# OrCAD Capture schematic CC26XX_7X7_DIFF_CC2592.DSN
size A3; title: TIDC-CC2650-CC2592-EMK; rev: Rev 1.1.0
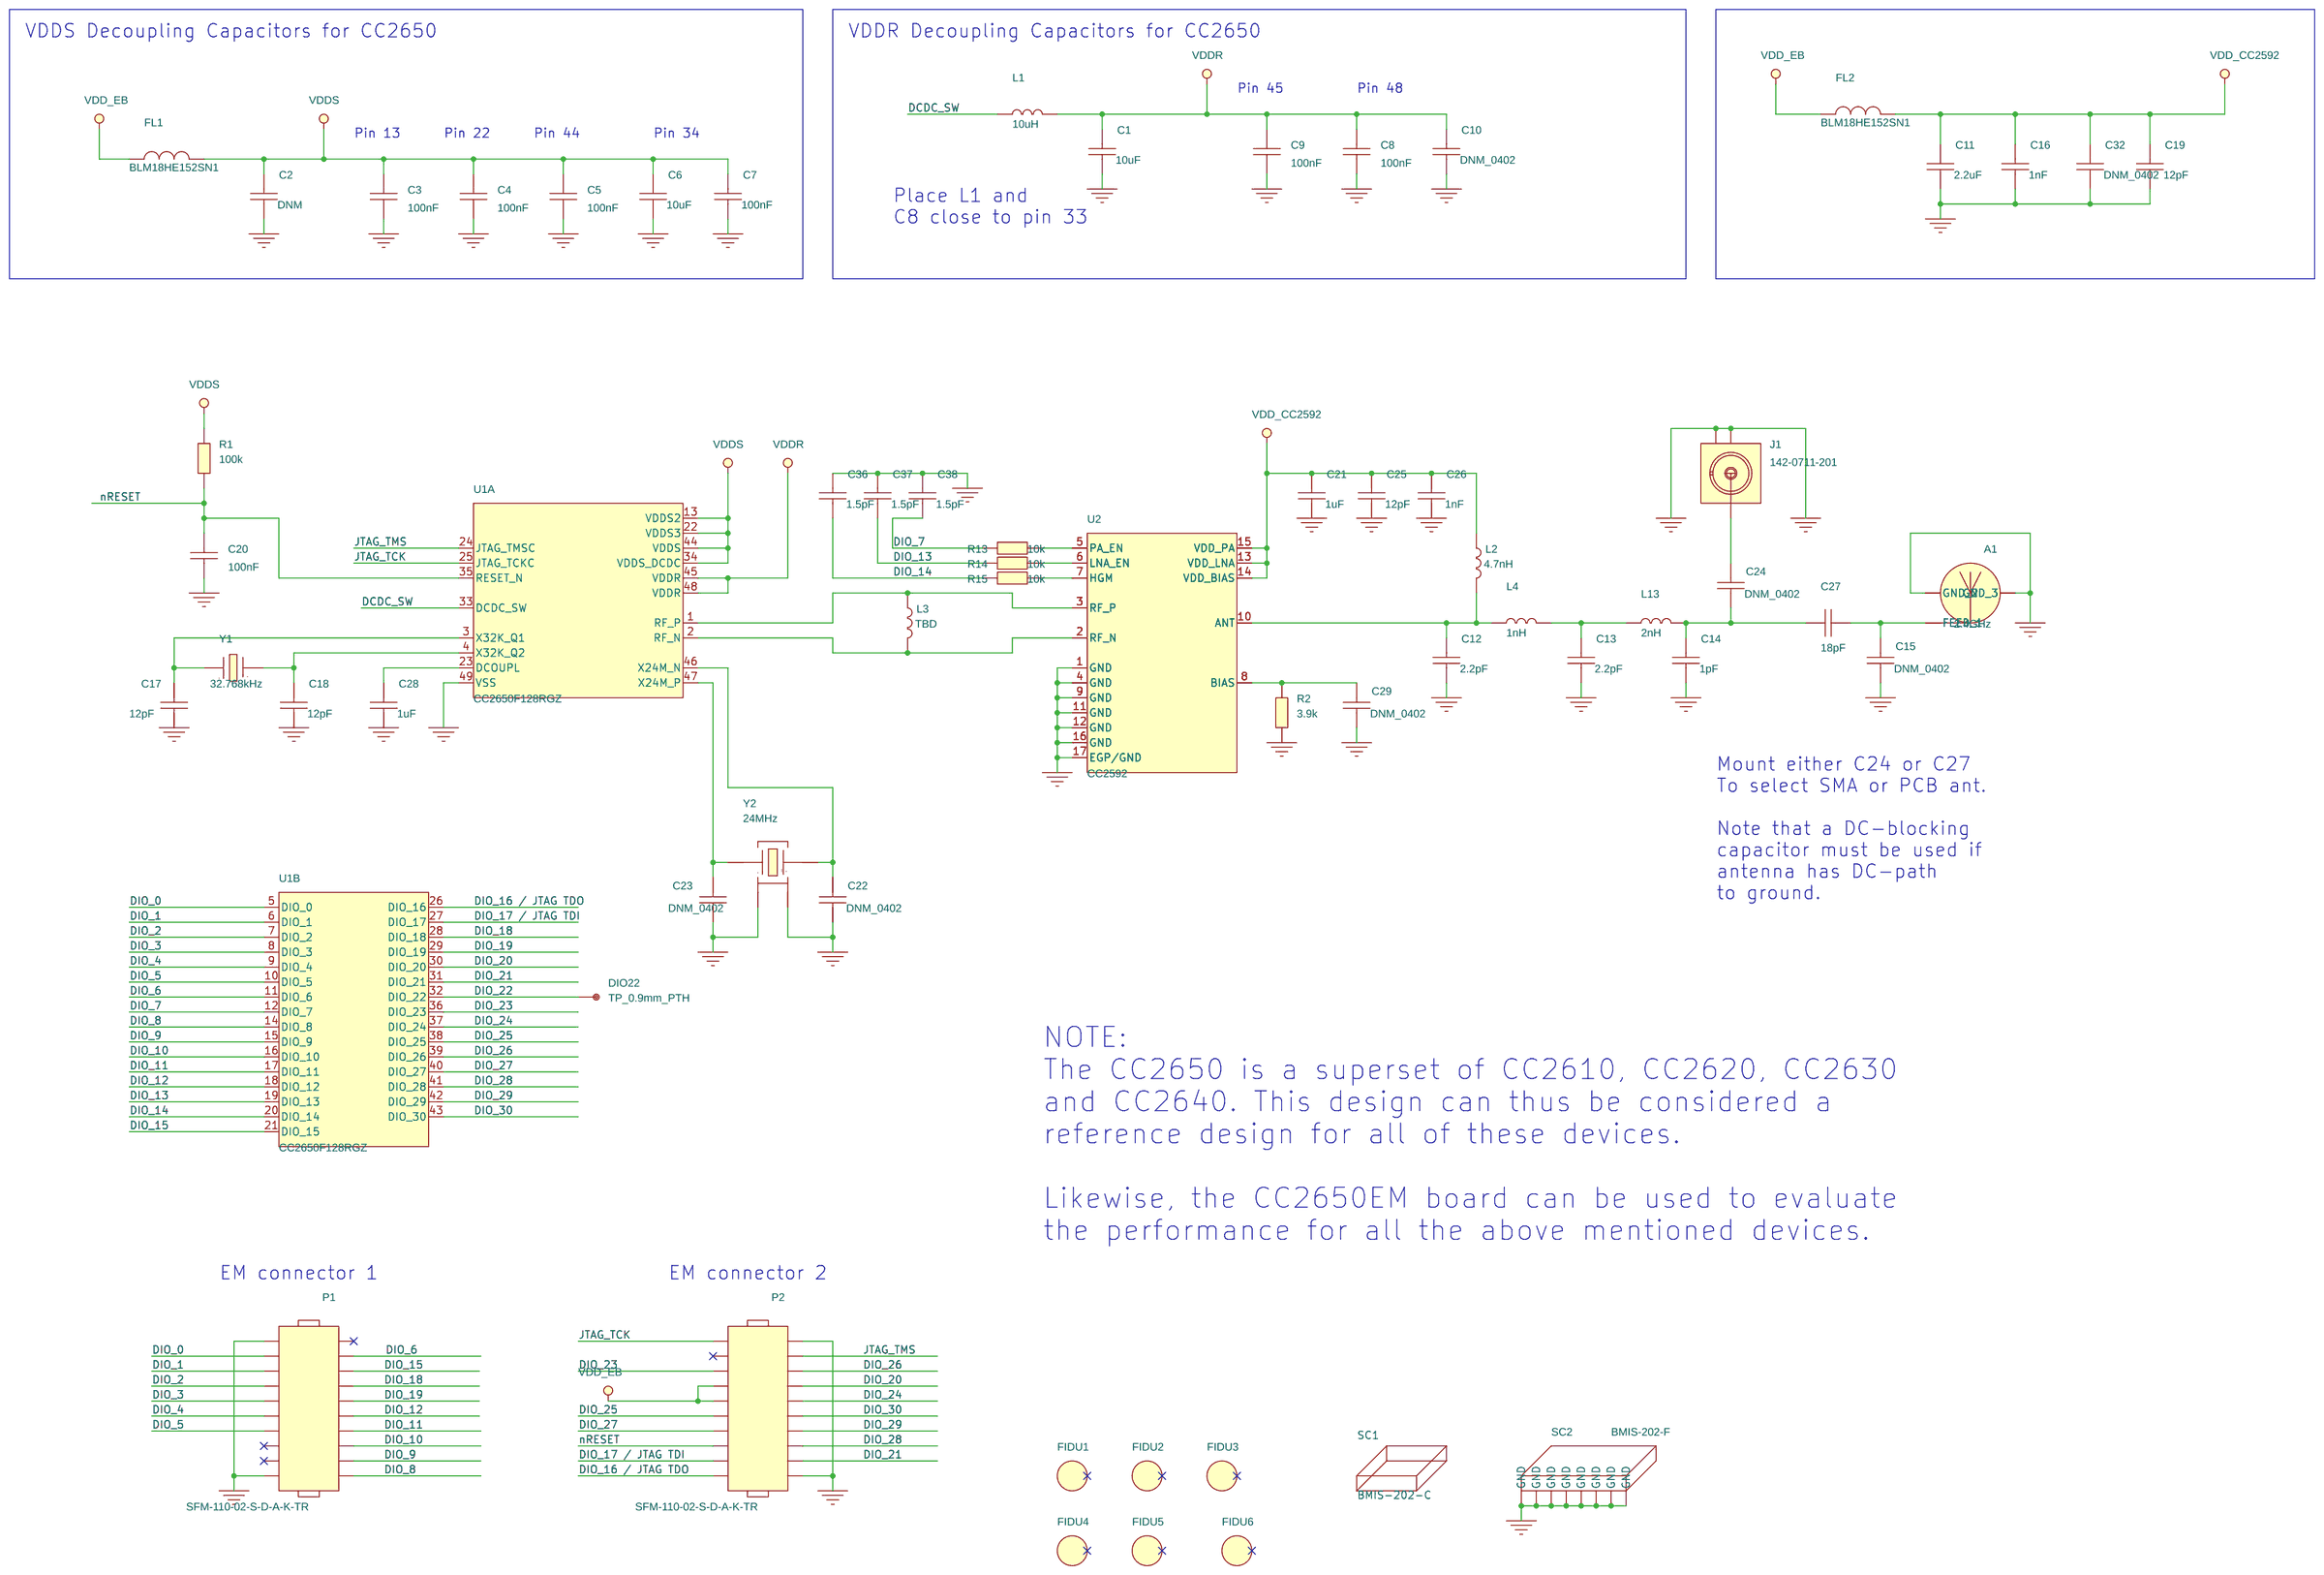
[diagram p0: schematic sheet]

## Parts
A1  2.4GHz  [ANTENNA_DN007N]
C1  10uF  [CAPC1608X90N]
C2  DNM  [CAPC1608X90N]
C3  100nF  [CAPC1005X60N]
C4  100nF  [CAPC1005X60N]
C5  100nF  [CAPC1005X60N]
C6  10uF  [CAPC1608X90N]
C7  100nF  [CAPC1608X90N]
C8  100nF  [CAPC1005X60N]
C9  100nF  [CAPC1005X60N]
C10  DNM_0402  [CAPC1005X60N]
C11  2.2uF  [CAPC1608X90N]
C12  2.2pF  [CAPC1005X60N]
C13  2.2pF  [CAPC1005X60N]
C14  1pF  [CAPC1005X60N]
C15  DNM_0402  [CAPC1005X60N]
C16  1nF  [CAPC1005X60N]
C17  12pF  [CAPC1005X60N]
C18  12pF  [CAPC1005X60N]
C19  12pF  [CAPC1005X60N]
C20  100nF  [CAPC1005X60N]
C21  1uF  [CAPC1005X60N]
C22  DNM_0402  [CAPC1005X60N]
C23  DNM_0402  [CAPC1005X60N]
C24  DNM_0402  [CAPC1005X60N]
C25  12pF  [CAPC1005X60N]
C26  1nF  [CAPC1005X60N]
C27  18pF  [CAPC1005X60N]
C28  1uF  [CAPC1005X60N]
C29  DNM_0402  [CAPC1005X60N]
C32  DNM_0402  [CAPC1005X60N]
C36  1.5pF  [CAPC1005X60N]
C37  1.5pF  [CAPC1005X60N]
C38  1.5pF  [CAPC1005X60N]
DIO22  TP_0.9mm_PTH  [TP150_90H]
FIDU1  FIDU_1MM  [FID100X115B]
FIDU2  FIDU_1MM  [FID100X115B]
FIDU3  FIDU_1MM  [FID100X115B]
FIDU4  FIDU_1MM  [FID100X115B]
FIDU5  FIDU_1MM  [FID100X115B]
FIDU6  FIDU_1MM  [FID100X115B]
FL1  BLM18HE152SN1  [FIL_BLM18HE152SN1DN]
FL2  BLM18HE152SN1  [FIL_BLM18HE152SN1DN]
J1  142-0711-201  [CINCH_1420711201_A2N]
L1  10uH  [INDC2012X150N]
L2  4.7nH  [INDC1005X60N]
L3  TBD  [INDC1005X60N]
L4  1nH  [INDC1005X60N]
L13  2nH  [INDC1005X60N]
P1  SFM-110-02-S-D-A-K-TR  [SAMTEC_SFM11002AN]
P2  SFM-110-02-S-D-A-K-TR  [SAMTEC_SFM11002AN]
R1  100k  [RESC1005X40N]
R2  3.9k  [RESC1005X40N]
R13  10k  [RESC1005X40N]
R14  10k  [RESC1005X40N]
R15  10k  [RESC1005X40N]
SC1  BMIS-202-C  [MECH_BMIS202CN]
SC2  BMIS-202-F  [MECH_BMIS202FN]
U1  CC2650F128RGZ  [QFNFC50P700X700X80-49CN]  (sections A,B)
U2  CC2592  [QFNFC65P400X400X100-17AN]
Y1  32.768kHz  [XTAL_FC-135N]
Y2  24MHz  [OSCCC250X320X60-4N]

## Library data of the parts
A1 = ANTENNA_DN007: ANTENNA, NON COMPONENT, 2.4GHz INVERTED F ANTENNA, NOT APPLY; AutoDoc File: http://notefied-dynamic-precision.com/DB/Apps/Desktop/Item/Object.aspx?id=85542; Budget Currency: N/A; Budget Price: N/A; Datasheet URL 1: N/A; Datasheet URL 2: http://www.ti.com/lit/an/swru120b/swru120b.pdf; Definied Quality: INDUSTRIAL; Esd Level: N/A; FPLIST: ANTENNA_DN007N,ANTENNA_DN007AN; Last Time Buy: N/A; Lead Time: N/A; LifeCycle Status: ACTIVE; MPN: DN007; MPN Status: ACTIVE; MSL: N/A; MTBF: N/A; MTBF Standard: N/A; Manufacturer: TEXAS INSTRUMENTS; Max Oper Temp: +85DEGC; Min Oper Temp: -40DEGC; Mounting Type: NOT APPLY; NOTE Status: PREFERRED; Old Footprint: ANTENNA_DN007N,ANTENNA_DN007AN; Packing Size: N/A; Packing Type: N/A; Part Number: 13-00347; Part Type: MECHANIC\ANTENNA\NON_COMPONENT; Revision: R008; RoHS Status: NOT_APPLICABLE; WEIGHT: N/A
C1 C6 = CAPACITOR: CAPACITOR, CERAMIC X5R, 10uF, 6.3V, -20%/+20%, -55DEGC/+85DEGC, 0603, SMD; ALT_SYMBOLS: CAPC1608X90L,CAPC1608X90M; AutoDoc File: http://notefied-dynamic-precision.com/DB/Apps/Desktop/Item/Object.aspx?id=74686; Budget Currency: EUR; Budget Price: 0.113; Datasheet URL 1: http://search.murata.co.jp/Ceramy/image/img/w_hinm/L0005E.pdf; Datasheet URL 2: http://psearch.murata.com/capacitor/product/GRM188R60J106ME47%23.pdf; Definied Quality: INDUSTRIAL; Dielectric Type: X5R; Esd Level: N/A; FPLIST: CAPC1608X90N,CAPC1608X90L,CAPC1608X90M; Last Time Buy: N/A; Lead Time: 20; LifeCycle Status: NRND; MPN: GRM188R60J106ME47D; MPN Status: NRND; MSL: 1; MTBF: N/A; MTBF Standard: N/A; Manufacturer: MURATA; Max Oper Temp: +85DEGC; Max Tol: +20%; Min Oper Temp: -55DEGC; Min Tol: -20%; Mounting Type: SMD; NOTE Status: PREFERRED; PCB Package: 0603; Packing Size: 4000; Packing Type: TAPE_&_REEL; Part Number: 02-02419; Part Type: CAPACITOR\CERAMIC\0603\STANDARD; Revision: R003; RoHS Status: ROHS_COMPLIANT; Rtd Voltage: 6.3V; WEIGHT: 0.0063g
C2 = CAPACITOR: CAPACITOR, DO NOT MOUNT, 0603, SMD; ALT_SYMBOLS: CAPC1608X90L,CAPC1608X90M; AutoDoc File: http://notefied-dynamic-precision.com/DB/Apps/Desktop/Item/Object.aspx?id=50475; FPLIST: CAPC1608X90N,CAPC1608X90L,CAPC1608X90M; Old Footprint: CAPC1608X90N,0603; Part Number: 02-01324; Part Type: NON_COMPONENT\DNM; Revision: R003
C3-C5 C8 C9 C20 = CAPACITOR: CAPACITOR, CERAMIC X7R, 100nF, 6.3V, -10%/+10%, -55DEGC/+125DEGC, 0402, SMD; ALT_SYMBOLS: CAPC1005X60L,CAPC1005X60M; AutoDoc File: http://notefied-dynamic-precision.com/DB/Apps/Desktop/Item/Object.aspx?id=73748; Budget Currency: EUR; Budget Price: 0.007; Datasheet URL 1: http://search.murata.co.jp/Ceramy/image/img/w_hinm/L0005E.pdf; Datasheet URL 2: http://psearch.murata.com/capacitor/product/GRM155R70J104KA01%23.pdf; Definied Quality: INDUSTRIAL; Dielectric Type: X7R; Esd Level: N/A; FPLIST: CAPC1005X60N,CAPC1005X60L,CAPC1005X60M; Last Time Buy: N/A; Lead Time: 14; LifeCycle Status: NRND; MPN: GRM155R70J104KA01D; MPN Status: NRND; MSL: 1; MTBF: N/A; MTBF Standard: N/A; Manufacturer: MURATA; Max Oper Temp: +125DEGC; Max Tol: +10%; Min Oper Temp: -55DEGC; Min Tol: -10%; Mounting Type: SMD; NOTE Status: PREFERRED; Old Footprint: CAPC1005X60N,0402; PCB Package: 0402; Packing Size: 10000; Packing Type: TAPE_&_REEL; Part Number: 02-02323; Part Type: CAPACITOR\CERAMIC\0402\STANDARD; Revision: R000; RoHS Status: ROHS_COMPLIANT; Rtd Voltage: 6.3V; WEIGHT: 0.0016g
C7 = CAPACITOR: CAPACITOR, CERAMIC X7R, 100nF, 25V, -10%/+10%, -55DEGC/+125DEGC, 0603, SMD; ALT_SYMBOLS: CAPC1608X90L,CAPC1608X90M; AutoDoc File: http://notefied-dynamic-precision.com/DB/Apps/Desktop/Item/Object.aspx?id=72070; Budget Currency: EUR; Budget Price: 0.005; Cage Code: C0151; Datasheet URL 1: http://search.murata.co.jp/Ceramy/image/img/w_hinm/L0005E.pdf; Datasheet URL 2: http://psearch.murata.com/capacitor/product/GRM188R71E104KA01%23.pdf; Definied Quality: INDUSTRIAL; Dielectric Type: X7R; Esd Level: N/A; FPLIST: CAPC1608X90N,CAPC1608X90L,CAPC1608X90M; Last Time Buy: N/A; Lead Time: 15; LifeCycle Status: NRND; MPN: GRM188R71E104KA01D; MPN Status: NRND; MSL: 1; MTBF: N/A; MTBF Standard: N/A; Manufacturer: MURATA; Max Oper Temp: +125DEGC; Max Tol: +10%; Min Oper Temp: -55DEGC; Min Tol: -10%; Mounting Type: SMD; NOTE Status: PREFERRED; Old Footprint: CAPC1608X90N,0603; PCB Package: 0603; Packing Size: 4000; Packing Type: TAPE_&_REEL; Part Number: 02-01992; Part Type: CAPACITOR\CERAMIC\0603\STANDARD; Revision: R001; RoHS Status: ROHS_COMPLIANT; Rtd Voltage: 25V; WEIGHT: 0.0063g
C10 C15 C22-C24 C29 = CAPACITOR: CAPACITOR, CERAMIC, TBD, -55DEGC/+125DEGC, 0402, DNM, SMD; ALT_SYMBOLS: CAPC1005X60L,CAPC1005X60M; AutoDoc File: http://notefied-dynamic-precision.com/DB/Apps/Desktop/Item/Object.aspx?id=84862; Budget Currency: USD; Budget Price: 0.00589; Datasheet URL 1: N/A; Datasheet URL 2: N/A; Definied Quality: INDUSTRIAL; Dielectric Type: MISSING-INFO; Esd Level: N/A; FPLIST: CAPC1005X60N,CAPC1005X60L,CAPC1005X60M; Last Time Buy: N/A; Lead Time: N/A; LifeCycle Status: ACTIVE; MPN: CAPACITOR_0402_DNM_N/A_M; MPN Status: ACTIVE; MSL: N/A; MTBF: N/A; MTBF Standard: N/A; Manufacturer: MANUFACTURER SELECTION; Max Oper Temp: +125DEGC; Min Oper Temp: -55DEGC; Mounting Type: SMD; NOTE Status: PREFERRED; PCB Package: 0402; Packing Size: 10000; Packing Type: TAPE_&_REEL; Part Number: 02-04164; Part Type: CAPACITOR\CERAMIC\0402\STANDARD; Revision: R000; RoHS Status: MISSING_INFO; WEIGHT: N/A
C11 = CAPACITOR: CAPACITOR, CERAMIC X5R, 2.2uF, 10V, -20%/+20%, -55DEGC/+85DEGC, 0603, SMD; ALT_SYMBOLS: CAPC1608X90L,CAPC1608X90M; AutoDoc File: http://notefied-dynamic-precision.com/DB/Apps/Desktop/Item/Object.aspx?id=50283; Budget Currency: EUR; Budget Price: 0.032; Datasheet URL 1: http://search.murata.co.jp/Ceramy/image/img/w_hinm/L0005E.pdf; Datasheet URL 2: http://psearch.murata.com/capacitor/product/GRM188R61A225ME34%23.pdf; Definied Quality: INDUSTRIAL; Dielectric Type: X5R; Esd Level: N/A; Last Time Buy: N/A; Lead Time: 20; LifeCycle Status: NRND; MPN: GRM188R61A225ME34D; MPN Status: NRND; MSL: 1; MTBF: N/A; MTBF Standard: N/A; Manufacturer: MURATA; Max Oper Temp: +85DEGC; Max Tol: +20%; Min Oper Temp: -55DEGC; Min Tol: -20%; Mounting Type: SMD; NOTE Status: PREFERRED; Old Footprint: CAPC1608X90N,0603; PCB Package: 0603; Packing Size: 4000; Packing Type: TAPE_&_REEL; Part Number: 02-01132; Part Type: CAPACITOR\CERAMIC\0603\STANDARD; Revision: R002; RoHS Status: ROHS_COMPLIANT; Rtd Voltage: 10V; WEIGHT: 0.0063g
C12 C13 = CAPACITOR: CAPACITOR, CERAMIC C0G/NP0, 2.2pF, 50V, -0.25pF/+0.25pF, -55DEGC/+125DEGC, 0402, SMD; ALT_SYMBOLS: CAPC1005X60L,CAPC1005X60M; AutoDoc File: http://notefied-dynamic-precision.com/DB/Apps/Desktop/Item/Object.aspx?id=87251; Budget Currency: EUR; Budget Price: 0.007; Datasheet URL 1: http://search.murata.co.jp/Ceramy/image/img/w_hinm/L0005E.pdf; Datasheet URL 2: http://psearch.murata.com/capacitor/product/GRM1555C1H2R2CA01%23.pdf; Definied Quality: INDUSTRIAL; Dielectric Type: C0G/NP0; Esd Level: N/A; Last Time Buy: N/A; Lead Time: 12; LifeCycle Status: ACTIVE; MPN: GRM1555C1H2R2CA01D; MPN Status: ACTIVE; MSL: 1; MTBF: N/A; MTBF Standard: N/A; Manufacturer: MURATA; Max Oper Temp: +125DEGC; Max Tol: +0.25pF; Min Oper Temp: -55DEGC; Min Tol: -0.25pF; Mounting Type: SMD; NOTE Status: PREFERRED; PCB Package: 0402; Packing Size: 10000; Packing Type: TAPE_&_REEL; Part Number: 02-04605; Part Type: CAPACITOR\CERAMIC\0402\STANDARD; Revision: R001; RoHS Status: ROHS_COMPLIANT; Rtd Voltage: 50V; WEIGHT: 0.0016g
C14 = CAPACITOR: CAPACITOR, CERAMIC C0G/NP0, 1pF, 50V, -0.25pF/ +0.25pF, -55DEGC/+125DEGC, 0402, SMD; ALT_SYMBOLS: CAPC1005X60L,CAPC1005X60M; AutoDoc File: http://notefied-dynamic-precision.com/DB/Apps/Desktop/Item/Object.aspx?id=87790; Budget Currency: EUR; Budget Price: 0.006; Datasheet URL 1: http://search.murata.co.jp/Ceramy/image/img/w_hinm/L0005E.pdf; Datasheet URL 2: http://psearch.murata.com/capacitor/product/GRM1555C1H1R0CA01%23.pdf; Definied Quality: INDUSTRIAL; Dielectric Type: C0G/NP0; Esd Level: N/A; Last Time Buy: N/A; Lead Time: 12; LifeCycle Status: ACTIVE; MPN: GRM1555C1H1R0CA01D; MPN Status: ACTIVE; MSL: 1; MTBF: N/A; MTBF Standard: N/A; Manufacturer: MURATA; Max Oper Temp: +125DEGC; Max Tol: +0.25pF; Min Oper Temp: -55DEGC; Min Tol: -0.25pF; Mounting Type: SMD; NOTE Status: PREFERRED; PCB Package: 0402; Packing Size: 10000; Packing Type: TAPE_&_REEL; Part Number: 02-04672; Part Type: CAPACITOR\CERAMIC\0402\STANDARD; Revision: R001; RoHS Status: ROHS_COMPLIANT; Rtd Voltage: 50V; WEIGHT: 0.0016g
C16 = CAPACITOR: CAPACITOR, CERAMIC X7R, 1nF, 50V, -5%/+5%, -55DEGC/+125DEGC, 0402, SMD; ALT_SYMBOLS: CAPC1005X60L,CAPC1005X60M; AutoDoc File: http://notefied-dynamic-precision.com/DB/Apps/Desktop/Item/Object.aspx?id=80112; Budget Currency: USD; Budget Price: 0.00589; Datasheet URL 1: N/A; Datasheet URL 2: N/A; Definied Quality: INDUSTRIAL; Dielectric Type: X7R; Esd Level: N/A; Last Time Buy: N/A; Lead Time: N/A; LifeCycle Status: ACTIVE; MPN: CAPACITOR_0402_1nF_X7R_M_+/-5%_50V; MPN Status: ACTIVE; MSL: N/A; MTBF: N/A; MTBF Standard: N/A; Manufacturer: MANUFACTURER SELECTION; Max Oper Temp: +125DEGC; Max Tol: +5%; Min Oper Temp: -55DEGC; Min Tol: -5%; Mounting Type: SMD; NOTE Status: PREFERRED; PCB Package: 0402; Packing Size: 10000; Packing Type: TAPE_&_REEL; Part Number: 02-03019; Part Type: CAPACITOR\CERAMIC\0402\STANDARD; Revision: R001; RoHS Status: ROHS_COMPLIANT; Rtd Voltage: 50V; WEIGHT: N/A
C17 C18 = CAPACITOR: CAPACITOR, CERAMIC C0G/NP0, 12pF, 50V, -5%/+5%, -55DEGC/+125DEGC, 0402, SMD; ALT_SYMBOLS: CAPC1005X60L,CAPC1005X60M; AutoDoc File: http://notefied-dynamic-precision.com/DB/Apps/Desktop/Item/Object.aspx?id=80123; Budget Currency: USD; Budget Price: 0.00589; Datasheet URL 1: N/A; Datasheet URL 2: N/A; Definied Quality: INDUSTRIAL; Dielectric Type: C0G/NP0; Esd Level: N/A; FPLIST: CAPC1005X60N,CAPC1005X60L,CAPC1005X60M; Last Time Buy: N/A; Lead Time: N/A; LifeCycle Status: ACTIVE; MPN: CAPACITOR_0402_12pF_C0G/NP0_M_+/-5%_50V; MPN Status: ACTIVE; MSL: N/A; MTBF: N/A; MTBF Standard: N/A; Manufacturer: MANUFACTURER SELECTION; Max Oper Temp: +125DEGC; Max Tol: +5%; Min Oper Temp: -55DEGC; Min Tol: -5%; Mounting Type: SMD; NOTE Status: PREFERRED; PCB Package: 0402; Packing Size: 10000; Packing Type: TAPE_&_REEL; Part Number: 02-03030; Part Type: CAPACITOR\CERAMIC\0402\STANDARD; Revision: R000; RoHS Status: ROHS_COMPLIANT; Rtd Voltage: 50V; WEIGHT: N/A
C19 C25 = CAPACITOR: CAPACITOR, CERAMIC C0G/NP0, 12pF, 50V, -5%/+5%, -55DEGC/+125DEGC, 0402, SMD; ALT_SYMBOLS: CAPC1005X60L,CAPC1005X60M; AutoDoc File: http://notefied-dynamic-precision.com/DB/Apps/Desktop/Item/Object.aspx?id=84867; Budget Currency: EUR; Budget Price: 0.007; Datasheet URL 1: http://search.murata.co.jp/Ceramy/image/img/w_hinm/L0005E.pdf; Datasheet URL 2: http://psearch.murata.com/capacitor/product/GRM1555C1H120JA01%23.pdf; Definied Quality: INDUSTRIAL; Dielectric Type: C0G/NP0; Esd Level: N/A; Last Time Buy: N/A; Lead Time: 12; LifeCycle Status: ACTIVE; MPN: GRM1555C1H120JA01D; MPN Status: ACTIVE; MSL: 1; MTBF: N/A; MTBF Standard: N/A; Manufacturer: MURATA; Max Oper Temp: +125DEGC; Max Tol: +5%; Min Oper Temp: -55DEGC; Min Tol: -5%; Mounting Type: SMD; NOTE Status: PREFERRED; PCB Package: 0402; Packing Size: 10000; Packing Type: TAPE_&_REEL; Part Number: 02-04168; Part Type: CAPACITOR\CERAMIC\0402\STANDARD; Revision: R000; RoHS Status: ROHS_COMPLIANT; Rtd Voltage: 50V; WEIGHT: 0.0016g
C21 = CAPACITOR: CAPACITOR, CERAMIC X5R, 1uF, 10V, -10%/+10%, -55DEGC/+85DEGC, 0402, SMD; ALT_SYMBOLS: CAPC1005X60L,CAPC1005X60M; AutoDoc File: http://notefied-dynamic-precision.com/DB/Apps/Desktop/Item/Object.aspx?id=74236; Budget Currency: EUR; Budget Price: 0.019; Datasheet URL 1: http://search.murata.co.jp/Ceramy/image/img/w_hinm/L0005E.pdf; Datasheet URL 2: http://psearch.murata.com/capacitor/product/GRM155R61A105KE15%23.pdf; Definied Quality: INDUSTRIAL; Dielectric Type: X5R; Esd Level: N/A; Last Time Buy: N/A; Lead Time: 12; LifeCycle Status: NRND; MPN: GRM155R61A105KE15D; MPN Status: NRND; MSL: 1; MTBF: N/A; MTBF Standard: N/A; Manufacturer: MURATA; Max Oper Temp: +85DEGC; Max Tol: +10%; Min Oper Temp: -55DEGC; Min Tol: -10%; Mounting Type: SMD; NOTE Status: PREFERRED; Old Footprint: CAPC1005X60N,0402; PCB Package: 0402; Packing Size: 10000; Packing Type: TAPE_&_REEL; Part Number: 02-02381; Part Type: CAPACITOR\CERAMIC\0402\STANDARD; Revision: R005; RoHS Status: ROHS_COMPLIANT; Rtd Voltage: 10V; WEIGHT: 0.0016g
C26 = CAPACITOR: CAPACITOR, CERAMIC C0G/NP0, 1nF, 50V, -5%/+5%, -55DEGC/+125DEGC, 0402, SMD; ALT_SYMBOLS: CAPC1005X60L,CAPC1005X60M; AutoDoc File: http://notefied-dynamic-precision.com/DB/Apps/Desktop/Item/Object.aspx?id=88013; Budget Currency: USD; Budget Price: 0.00589; Datasheet URL 1: N/A; Datasheet URL 2: N/A; Definied Quality: INDUSTRIAL; Dielectric Type: C0G/NP0; Esd Level: N/A; Last Time Buy: N/A; Lead Time: N/A; LifeCycle Status: ACTIVE; MPN: CAPACITOR_0402_1nF_C0G/NP0_M_+/-5%_50V; MPN Status: ACTIVE; MSL: N/A; MTBF: N/A; MTBF Standard: N/A; Manufacturer: MANUFACTURER SELECTION; Max Oper Temp: +125DEGC; Max Tol: +5%; Min Oper Temp: -55DEGC; Min Tol: -5%; Mounting Type: SMD; NOTE Status: PREFERRED; PCB Package: 0402; Packing Size: 10000; Packing Type: TAPE_&_REEL; Part Number: 02-04728; Part Type: CAPACITOR\CERAMIC\0402\STANDARD; Revision: R001; RoHS Status: ROHS_COMPLIANT; Rtd Voltage: 50V; WEIGHT: N/A
C27 = CAPACITOR: CAPACITOR, CERAMIC C0G/NPO, 18pF, 50V, -55DEGC/+125DEGC, 0402, SMD; ALT_SYMBOLS: CAPC1005X60L,CAPC1005X60M; AutoDoc File: http://notefied-dynamic-precision.com/DB/Apps/Desktop/Item/Object.aspx?id=74533; Budget Currency: EUR; Budget Price: 0.007; Datasheet URL 1: http://search.murata.co.jp/Ceramy/image/img/w_hinm/L0005E.pdf; Datasheet URL 2: http://psearch.murata.com/capacitor/product/GRM1555C1H180JA01%23.pdf; Definied Quality: INDUSTRIAL; Dielectric Type: C0G/NP0; Esd Level: N/A; Last Time Buy: N/A; Lead Time: 12; LifeCycle Status: ACTIVE; MPN: GRM1555C1H180JA01D; MPN Status: ACTIVE; MSL: 1; MTBF: N/A; MTBF Standard: N/A; Manufacturer: MURATA; Max Oper Temp: +125DEGC; Max Tol: +5%; Min Oper Temp: -55DEGC; Min Tol: -5%; Mounting Type: SMD; NOTE Status: PREFERRED; PCB Package: 0402; Packing Size: 10000; Packing Type: TAPE_&_REEL; Part Number: 02-02407; Part Type: CAPACITOR\CERAMIC\0402\STANDARD; Revision: R002; RoHS Status: ROHS_COMPLIANT; Rtd Voltage: 50V; WEIGHT: 0.0016g
C28 = CAPACITOR: CAPACITOR, CERAMIC X5R, 1uF, 10V, -10%/+10%, -55DEGC/+85DEGC, 0402, SMD; ALT_SYMBOLS: CAPC1005X60L,CAPC1005X60M; AutoDoc File: http://notefied-dynamic-precision.com/DB/Apps/Desktop/Item/Object.aspx?id=74236; Budget Currency: EUR; Budget Price: 0.019; Datasheet URL 1: http://search.murata.co.jp/Ceramy/image/img/w_hinm/L0005E.pdf; Datasheet URL 2: http://psearch.murata.com/capacitor/product/GRM155R61A105KE15%23.pdf; Definied Quality: INDUSTRIAL; Dielectric Type: X5R; Esd Level: N/A; FPLIST: CAPC1005X60N,CAPC1005X60L,CAPC1005X60M; Last Time Buy: N/A; Lead Time: 12; LifeCycle Status: NRND; MPN: GRM155R61A105KE15D; MPN Status: NRND; MSL: 1; MTBF: N/A; MTBF Standard: N/A; Manufacturer: MURATA; Max Oper Temp: +85DEGC; Max Tol: +10%; Min Oper Temp: -55DEGC; Min Tol: -10%; Mounting Type: SMD; NOTE Status: PREFERRED; Old Footprint: CAPC1005X60N,0402; PCB Package: 0402; Packing Size: 10000; Packing Type: TAPE_&_REEL; Part Number: 02-02381; Part Type: CAPACITOR\CERAMIC\0402\STANDARD; Revision: R005; RoHS Status: ROHS_COMPLIANT; Rtd Voltage: 10V; WEIGHT: 0.0016g
C32 = CAPACITOR: CAPACITOR, CERAMIC, TBD, -55DEGC/+125DEGC, 0402, DNM, SMD; ALT_SYMBOLS: CAPC1005X60L,CAPC1005X60M; AutoDoc File: http://notefied-dynamic-precision.com/DB/Apps/Desktop/Item/Object.aspx?id=84862; Budget Currency: USD; Budget Price: 0.00589; Datasheet URL 1: N/A; Datasheet URL 2: N/A; Definied Quality: INDUSTRIAL; Dielectric Type: MISSING-INFO; Esd Level: N/A; Last Time Buy: N/A; Lead Time: N/A; LifeCycle Status: ACTIVE; MPN: CAPACITOR_0402_DNM_N/A_M; MPN Status: ACTIVE; MSL: N/A; MTBF: N/A; MTBF Standard: N/A; Manufacturer: MANUFACTURER SELECTION; Max Oper Temp: +125DEGC; Min Oper Temp: -55DEGC; Mounting Type: SMD; NOTE Status: PREFERRED; PCB Package: 0402; Packing Size: 10000; Packing Type: TAPE_&_REEL; Part Number: 02-04164; Part Type: CAPACITOR\CERAMIC\0402\STANDARD; Revision: R000; RoHS Status: MISSING_INFO; WEIGHT: N/A
C36-C38 = CAPACITOR: CAPACITOR, CERAMIC C0G/NP0, 1.5pF, 50V, -0.25pF/+0.25pF, -55DEGC/+125DEGC, 0402, SMD; ALT_SYMBOLS: CAPC1005X60L,CAPC1005X60M; AutoDoc File: http://notefied-dynamic-precision.com/DB/Apps/Desktop/Item/Object.aspx?id=87808; Budget Currency: EUR; Budget Price: 0.006; Datasheet URL 1: http://search.murata.co.jp/Ceramy/image/img/w_hinm/L0005E.pdf; Datasheet URL 2: http://psearch.murata.com/capacitor/product/GRM1555C1H1R5CA01%23.pdf; Definied Quality: INDUSTRIAL; Dielectric Type: C0G/NP0; Esd Level: N/A; Last Time Buy: N/A; Lead Time: 16; LifeCycle Status: ACTIVE; MPN: GRM1555C1H1R5CA01D; MPN Status: ACTIVE; MSL: 1; MTBF: N/A; MTBF Standard: N/A; Manufacturer: MURATA; Max Oper Temp: +125DEGC; Max Tol: +0.25pF; Min Oper Temp: -55DEGC; Min Tol: -0.25pF; Mounting Type: SMD; NOTE Status: PREFERRED; PCB Package: 0402; Packing Size: 10000; Packing Type: TAPE_&_REEL; Part Number: 02-04678; Part Type: CAPACITOR\CERAMIC\0402\STANDARD; Revision: R001; RoHS Status: ROHS_COMPLIANT; Rtd Voltage: 50V; WEIGHT: 0.0016g
DIO22 = TEST_POINT: NON COMPONENT, TEST POINT, HOLE 0.9mm, 1.5mm ETCH, PTH; AutoDoc File: http://notefied-dynamic-precision.com/DB/Apps/Desktop/Item/Object.aspx?id=84966; FPLIST: TP150_90H,; Part Number: 19-00299; Part Type: NON_COMPONENT\TEST_POINT; Revision: R001
FIDU1-FIDU6 = FIDMARK: NON COMPONENT, FIDUCIAL MARK, ROUND 1mm, SMD; AutoDoc File: http://notefied-dynamic-precision.com/DB/Apps/Desktop/Item/Object.aspx?id=74548; Part Number: 19-00111; Part Type: NON_COMPONENT\FIDUCIAL; Revision: R002
FL1 FL2 = FILTER_2PIN: FILTER, EMI, FERRITE BEAD, 1500@100MHz, -25%/+25%, -55DEGC/+125DEGC, 0603, SMD; ALT_SYMBOLS: FIL_BLM18HE152SN1DL,FIL_BLM18HE152SN1DM; AutoDoc File: http://notefied-dynamic-precision.com/DB/Apps/Desktop/Item/Object.aspx?id=85575; Budget Currency: EUR; Budget Price: 0.065; Datasheet URL 1: http://search.murata.co.jp/Ceramy/image/img/w_hinm/L0110E.pdf; Datasheet URL 2: http://search.murata.co.jp/Ceramy/image/img/PDF/ENG/L0110S0101BLM18H.pdf; Definied Quality: INDUSTRIAL; Esd Level: N/A; FPLIST: FIL_BLM18HE152SN1DN,FIL_BLM18HE152SN1DL,FIL_BLM18HE152SN1DM; Frequency: 100MHz; Impedance: 1500; Inductance: N/A; Last Time Buy: N/A; Lead Time: 9; LifeCycle Status: ACTIVE; MPN: BLM18HE152SN1D; MPN Status: ACTIVE; MSL: N/A; MTBF: N/A; MTBF Standard: N/A; Manufacturer: MURATA; Max Oper Temp: +125DEGC; Max Tol: +25%; Min Oper Temp: -55DEGC; Min Tol: -25%; Mounting Type: SMD; NOTE Status: PREFERRED; PCB Package: 0603; Packing Size: 4000; Packing Type: TAPE_&_REEL; Part Number: 04-00470; Part Type: FILTER\EMI\FERRITE_BEAD\0603; Revision: R001; RoHS Status: ROHS_COMPLIANT; Rtd Current: 0.5A; Rtd Voltage: N/A; WEIGHT: 0.006g
J1 = CONN_COAX_1_J_2MH_V1: CONNECTOR, COAX, RF, FEMALE, STRAIGHT, 1 PIN, SMD; ALT_SYMBOLS: CINCH_1420711201_A2L,CINCH_1420711201_A2M; AutoDoc File: http://notefied-dynamic-precision.com/DB/Apps/Desktop/Item/Object.aspx?id=104381; Budget Currency: USD; Budget Price: 3.3496; Datasheet URL 1: https://cinchconnectivity.com/OA_MEDIA/drawings/dr-1420711201.pdf; Datasheet URL 2: https://cinchconnectivity.com/OA_MEDIA/specs/pi-142-0711-201.pdf; Definied Quality: MILITARY; Frequency: 18GHz; Impedance: 50; Last Time Buy: N/A; Lead Time: 6; LifeCycle Status: ACTIVE; MPN Status: ACTIVE; MSL: N/A; Manufacturer: CINCH CONNECTIVITY; Max Oper Temp: +165DEGC; Min Oper Temp: -65DEGC; Mounting Type: SMD; NOTE Status: PREFERRED; No Of Pos: 1; Packing Size: 25; Packing Type: BULK; Part Number: 06-04996; Part Type: CONNECTOR\COAX\RF; Revision: R001; RoHS Status: ROHS_COMPLIANT
L1 = INDUCTOR: INDUCTOR, STANDARD, CHIP, FERRITE CORE, 10uH, -20%/+20%, 0.11A, -40DEGC/+85DEGC, 0805, SMD; ALT_SYMBOLS: INDC2012X150L,INDC2012X150M; AutoDoc File: http://notefied-dynamic-precision.com/DB/Apps/Desktop/Item/Object.aspx?id=84960; Budget Currency: EUR; Budget Price: 0.062; Datasheet URL 1: N/A; Datasheet URL 2: http://ds.yuden.co.jp/TYCOMPAS/ut/detail.do?productNo=CKS2125100M-T&dataUnit=M; Definied Quality: INDUSTRIAL; Esd Level: N/A; Frequency: 24MHz; Last Time Buy: N/A; Lead Time: 5; LifeCycle Status: ACTIVE; MPN: CKS2125100M-T; MPN Status: ACTIVE; MSL: N/A; MTBF: N/A; MTBF Standard: N/A; Manufacturer: TAIYO YUDEN; Max Oper Temp: +85DEGC; Max Tol: +20%; Min Oper Temp: -40DEGC; Min Tol: -20%; Mounting Type: SMD; NOTE Status: PREFERRED; PCB Package: 0805; Packing Size: 2000; Packing Type: TAPE_&_REEL; Part Number: 03-06514; Part Type: INDUCTOR\STANDARD\CHIP\0805; Revision: R001; RoHS Status: ROHS_COMPLIANT; Rtd Current: 0.11A; WEIGHT: N/A
L2 = INDUCTOR: INDUCTOR, RF, CHIP, NON-MAGNETIC CORE, 4.7nH, -0.3nH/+0.3nH, 0.3A, -55DEGC/+125DEGC, 0402, SMD; ALT_SYMBOLS: INDC1005X60L,INDC1005X60M; AutoDoc File: http://notefied-dynamic-precision.com/DB/Apps/Desktop/Item/Object.aspx?id=87735; Budget Currency: EUR; Budget Price: 0.03; Datasheet URL 1: N/A; Datasheet URL 2: http://psearch.murata.com/inductor/product/LQG15HS4N7S02%23.pdf; Definied Quality: INDUSTRIAL; Esd Level: N/A; Frequency: 6GHz; Last Time Buy: N/A; Lead Time: 9; LifeCycle Status: ACTIVE; MPN: LQG15HS4N7S02D; MPN Status: ACTIVE; MSL: N/A; MTBF: N/A; MTBF Standard: N/A; Manufacturer: MURATA; Max Oper Temp: +125DEGC; Max Tol: +0.3nH; Min Oper Temp: -55DEGC; Min Tol: -0.3nH; Mounting Type: SMD; NOTE Status: PREFERRED; PCB Package: 0402; Packing Size: 10000; Packing Type: TAPE_&_REEL; Part Number: 03-06631; Part Type: INDUCTOR\RF\CHIP\0402; Resistance: 0.18; Revision: R001; RoHS Status: ROHS_COMPLIANT; Rtd Current: 0.3A; WEIGHT: 0.001g
L3 = INDUCTOR: INDUCTOR, STANDARD, CHIP, TBD, 0402, SMD; ALT_SYMBOLS: INDC1005X60M,INDC1005X60L; AutoDoc File: http://notefied-dynamic-precision.com/DB/Apps/Desktop/Item/Object.aspx?id=45714; Budget Currency: N/A; Budget Price: N/A; Datasheet URL 1: N/A; Datasheet URL 2: N/A; Definied Quality: COMMERCIAL; Esd Level: N/A; Frequency: N/A; Inductance: N/A; Last Time Buy: N/A; Lead Time: N/A; LifeCycle Status: ACTIVE; MPN: IND_TBD_0402; MPN Status: ACTIVE; MSL: N/A; MTBF: N/A; MTBF Standard: N/A; Manufacturer: MANUFACTURER SELECTION; Max Oper Temp: N/A; Max Tol: N/A; Min Oper Temp: N/A; Min Tol: N/A; Mounting Type: SMD; NOTE Status: PREFERRED; Old Footprint: 0402; PCB Package: 0402; Packing Size: N/A; Packing Type: N/A; Part Number: 03-01022; Part Type: INDUCTOR\STANDARD\CHIP\0402; Resistance: N/A; Revision: R002; RoHS Status: ROHS_COMPLIANT; Rtd Current: N/A; WEIGHT: N/A
L4 = INDUCTOR: INDUCTOR, RF, CHIP, NON-MAGNETIC CORE, 1nH, -0.3nH/+0.3nH, 0.3A, -55DEGC/+125DEGC, 0402, SMD; ALT_SYMBOLS: INDC1005X60L,INDC1005X60M; AutoDoc File: http://notefied-dynamic-precision.com/DB/Apps/Desktop/Item/Object.aspx?id=87398; Budget Currency: EUR; Budget Price: 0.031; Datasheet URL 1: N/A; Datasheet URL 2: http://psearch.murata.com/inductor/product/LQG15HS1N0S02%23.pdf; Definied Quality: INDUSTRIAL; Esd Level: N/A; Frequency: 10GHz; Last Time Buy: N/A; Lead Time: 9; LifeCycle Status: ACTIVE; MPN: LQG15HS1N0S02D; MPN Status: ACTIVE; MSL: N/A; MTBF: N/A; MTBF Standard: N/A; Manufacturer: MURATA; Max Oper Temp: +125DEGC; Max Tol: +0.3nH; Min Oper Temp: -55DEGC; Min Tol: -0.3nH; Mounting Type: SMD; NOTE Status: PREFERRED; PCB Package: 0402; Packing Size: 10000; Packing Type: TAPE_&_REEL; Part Number: 03-06607; Part Type: INDUCTOR\RF\CHIP\0402; Resistance: 0.07; Revision: R001; RoHS Status: ROHS_COMPLIANT; Rtd Current: 0.3A; WEIGHT: 0.001g
L13 = INDUCTOR: INDUCTOR, RF, CHIP, NON-MAGNETIC CORE, 2nH, -0.3nH/+0.3nH, 0.3A, -55DEGC/+125DEGC, 0402, SMD; ALT_SYMBOLS: INDC1005X60L,INDC1005X60M; AutoDoc File: http://notefied-dynamic-precision.com/DB/Apps/Desktop/Item/Object.aspx?id=85431; Budget Currency: EUR; Budget Price: 0.031; Datasheet URL 1: N/A; Datasheet URL 2: http://psearch.murata.com/inductor/product/LQG15HS2N0S02%23.pdf; Definied Quality: INDUSTRIAL; Esd Level: N/A; FPLIST: INDC1005X60N,INDC1005X60L,INDC1005X60M; Frequency: 6GHz; Last Time Buy: N/A; Lead Time: 10; LifeCycle Status: ACTIVE; MPN: LQG15HS2N0S02D; MPN Status: ACTIVE; MSL: N/A; MTBF: N/A; MTBF Standard: N/A; Manufacturer: MURATA; Max Oper Temp: +125DEGC; Max Tol: +0.3nH; Min Oper Temp: -55DEGC; Min Tol: -0.3nH; Mounting Type: SMD; NOTE Status: PREFERRED; PCB Package: 0402; Packing Size: 10000; Packing Type: TAPE_&_REEL; Part Number: 03-06525; Part Type: INDUCTOR\RF\CHIP\0402; Revision: R001; RoHS Status: ROHS_COMPLIANT; Rtd Current: 0.3A; WEIGHT: 0.001g
P1 P2 = CONN_HEADER_2X10_P_S: CONNECTOR, HEADER, FEMALE, STRAIGHT, 2 ROWS, 20 PINS, PITCH 1.27mm, SMD; ALT_SYMBOLS: SAMTEC_SFM11002AL,SAMTEC_SFM11002AM; AutoDoc File: http://notefied-dynamic-precision.com/DB/Apps/Desktop/Item/Object.aspx?id=85603; Budget Currency: USD; Budget Price: 3.180; Datasheet URL 1: http://suddendocs.samtec.com/prints/sfm-1xx-xx-xxx-d-xxx-mkt.pdf; Datasheet URL 2: http://suddendocs.samtec.com/catalog_english/sfm.pdf; Definied Quality: INDUSTRIAL; Esd Level: N/A; Last Time Buy: N/A; Lead Time: 2; LifeCycle Status: ACTIVE; MPN: SFM-110-02-SM-D-A-K-TR; MPN Status: ACTIVE; MSL: N/A; MTBF: N/A; MTBF Standard: N/A; Manufacturer: SAMTEC; Max Oper Temp: +125DEGC; Min Oper Temp: -55DEGC; Mounting Type: SMD; NOTE Status: PREFERRED; No Of Pos: 20; No Of Rows: 2; Packing Size: 725; Packing Type: TAPE_&_REEL; Part Number: 06-02251; Part Type: CONNECTOR\HEADER\STANDARD; Pitch: 1.27mm; Revision: R001; RoHS Status: ROHS_COMPLIANT; WEIGHT: 0.30875g
R1 = RESISTOR: RESISTOR, THICK FILM, 100k, -1%/+1%, 0.063W, 50V, -55DEGC/+155DEGC, 0402, SMD; ALT_SYMBOLS: RESC1005X40L,RESC1005X40M; AutoDoc File: http://notefied-dynamic-precision.com/DB/Apps/Desktop/Item/Object.aspx?id=76892; Budget Currency: USD; Budget Price: 0.00244; Datasheet URL 1: N/A; Datasheet URL 2: N/A; Definied Quality: INDUSTRIAL; Esd Level: N/A; FPLIST: RESC1005X40N,RESC1005X40L,RESC1005X40M; Last Time Buy: N/A; Lead Time: N/A; LifeCycle Status: ACTIVE; MPN: RESISTOR_0402_100k_+/-1%_50V_0.063W_M_+/-100ppm; MPN Status: ACTIVE; MSL: N/A; MTBF: N/A; MTBF Standard: N/A; Manufacturer: MANUFACTURER SELECTION; Max Oper Temp: +155DEGC; Max TC: +100PPM/DEGC; Max Tol: +1%; Min Oper Temp: -55DEGC; Min TC: -100PPM/DEGC; Min Tol: -1%; Mounting Type: SMD; NOTE Status: PREFERRED; PCB Package: 0402; Packing Size: 10000; Packing Type: TAPE_&_REEL; Part Number: 01-12837; Part Type: RESISTOR\0402\PRECISION; Resistor Type: THICK FILM; Revision: R002; RoHS Status: ROHS_COMPLIANT; Rtd Current: N/A; Rtd Power: 0.063W; Rtd Voltage: 50V; WEIGHT: N/A
R2 = RESISTOR: RESISTOR, THICK FILM, 3.9k, -1%/+1%, 0.063W, 50V, -55DEGC/+155DEGC, 0402, SMD; ALT_SYMBOLS: RESC1005X40L,RESC1005X40M; AutoDoc File: http://notefied-dynamic-precision.com/DB/Apps/Desktop/Item/Object.aspx?id=76730; Budget Currency: USD; Budget Price: 0.00244; Datasheet URL 1: N/A; Datasheet URL 2: N/A; Definied Quality: INDUSTRIAL; Esd Level: N/A; Last Time Buy: N/A; Lead Time: N/A; LifeCycle Status: ACTIVE; MPN: RESISTOR_0402_3.9k_+/-1%_50V_0.063W_M_+/-100ppm; MPN Status: ACTIVE; MSL: N/A; MTBF: N/A; MTBF Standard: N/A; Manufacturer: MANUFACTURER SELECTION; Max Oper Temp: +155DEGC; Max TC: +100PPM/DEGC; Max Tol: +1%; Min Oper Temp: -55DEGC; Min TC: -100PPM/DEGC; Min Tol: -1%; Mounting Type: SMD; NOTE Status: PREFERRED; PCB Package: 0402; Packing Size: 10000; Packing Type: TAPE_&_REEL; Part Number: 01-12675; Part Type: RESISTOR\0402\PRECISION; Resistor Type: THICK FILM; Revision: R000; RoHS Status: ROHS_COMPLIANT; Rtd Current: N/A; Rtd Power: 0.063W; Rtd Voltage: 50V; WEIGHT: N/A
R13-R15 = RESISTOR: RESISTOR, THICK FILM, 10k, -5%/+5%, 0.063W, 50V, -55DEGC/+155DEGC, 0402, SMD; ALT_SYMBOLS: RESC1005X40L,RESC1005X40M; AutoDoc File: http://notefied-dynamic-precision.com/DB/Apps/Desktop/Item/Object.aspx?id=47128; Budget Currency: EUR; Budget Price: 0.007; Datasheet URL 1: N/A; Datasheet URL 2: http://www.vishay.com/docs/20035/dcrcwe3.pdf; Definied Quality: INDUSTRIAL; Esd Level: N/A; Last Time Buy: N/A; Lead Time: 14; LifeCycle Status: ACTIVE; MPN: CRCW040210K0JNED; MPN Status: ACTIVE; MSL: 1; MTBF: 1.00*10^10; MTBF Standard: CL=90%; Manufacturer: VISHAY; Max Oper Temp: +155DEGC; Max TC: +200PPM/DEGC; Max Tol: +5%; Min Oper Temp: -55DEGC; Min TC: -200PPM/DEGC; Min Tol: -5%; Mounting Type: SMD; NOTE Status: PREFERRED; Old Footprint: RESC1005X40N,0402; PCB Package: 0402; Packing Size: 10000; Packing Type: TAPE_&_REEL; Part Number: 01-01244; Part Type: RESISTOR\0402\STANDARD; Resistor Type: THICK FILM; Revision: R001; RoHS Status: ROHS_COMPLIANT; Rtd Current: N/A; Rtd Power: 0.063W; Rtd Voltage: 50V; WEIGHT: 0.00065g
SC1 = SHIELD_COVER_BMIS-202C: MECHANIC, COVER FOR SHIELD BMI-S-202; AutoDoc File: http://notefied-dynamic-precision.com/DB/Apps/Desktop/Item/Object.aspx?id=90885; Budget Currency: USD; Budget Price: 1.02; Datasheet URL 1: http://www.lairdtech.com/brandworld/library/EMI-CAT-Essentials%201213.pdf; Datasheet URL 2: http://www.lairdtech.com/brandworld/library/Board%20Level%20Shields%20Catalog%20Download.pdf; Definied Quality: MILITARY; Esd Level: N/A; Last Time Buy: N/A; Lead Time: 8; LifeCycle Status: ACTIVE; MPN: BMI-S-202-C; MPN Status: ACTIVE; MSL: N/A; MTBF: N/A; MTBF Standard: N/A; Manufacturer: LAIRD; Max Oper Temp: +85DEGC; Min Oper Temp: -40DEGC; Mounting Type: NOT APPLY; NOTE Status: PREFERRED; Packing Size: 700; Packing Type: BULK; Part Number: 13-00498; Part Type: MECHANIC\SHIELD; Revision: R001; RoHS Status: ROHS_COMPLIANT; WEIGHT: 0.5g
SC2 = SHIELD_COVER_BMIS-202: MECHANIC, FRAME FOR SHIELD BMI-S-202; AutoDoc File: http://notefied-dynamic-precision.com/DB/Apps/Desktop/Item/Object.aspx?id=90859; Budget Currency: USD; Budget Price: 1.10; Datasheet URL 1: http://www.lairdtech.com/brandworld/library/EMI-CAT-Essentials%201213.pdf; Datasheet URL 2: http://www.lairdtech.com/brandworld/library/Board%20Level%20Shields%20Catalog%20Download.pdf; Definied Quality: MILITARY; Esd Level: N/A; Last Time Buy: N/A; Lead Time: 5; LifeCycle Status: ACTIVE; MPN: BMI-S-202-F; MPN Status: ACTIVE; MSL: N/A; MTBF: N/A; MTBF Standard: N/A; Manufacturer: LAIRD; Max Oper Temp: +85DEGC; Min Oper Temp: -40DEGC; Mounting Type: SMD; NOTE Status: PREFERRED; Packing Size: 700; Packing Type: TAPE_&_REEL; Part Number: 13-00497; Part Type: MECHANIC\SHIELD; Revision: R001; RoHS Status: ROHS_COMPLIANT; WEIGHT: N/A
U1 = IC_RF_CC26XX_QFN48_V2: IC, MICROCONTROLLER, 2.4GHZ SIMPLELINK WIRELESS MCU, PITCH 0,5MM, QFN48, SMD; ALT_SYMBOLS: QFNFC50P700X700X80-49CL,QFNFC50P700X700X80-49CM; AutoDoc File: http://notefied-dynamic-precision.com/DB/Apps/Desktop/Item/Object.aspx?id=88778; Budget Currency: USD; Budget Price: 4.56; Datasheet URL 1: http://www.ti.com/litv/pdf/mpqf123e; Datasheet URL 2: http://www.ti.com/lit/ds/symlink/cc2650.pdf; Definied Quality: INDUSTRIAL; Esd Level: N/A; FPLIST: QFNFC50P700X700X80-49CN,QFNFC50P700X700X80-49CL,QFNFC50P700X700X80-49CM; Last Time Buy: N/A; Lead Time: 6; LifeCycle Status: PRELIMINARY; MPN: CC2650F128RGZT; MPN Status: PRELIMINARY; MSL: 3; MTBF: 4.153*10^8; MTBF Standard: CL=60%,Tu=55degC,Ea=0.7eV,Tt=125degC; Manufacturer: TEXAS INSTRUMENTS; Max Oper Temp: +85DEGC; Min Oper Temp: -40DEGC; Mounting Type: SMD; NOTE Status: PREFERRED; PCB Package: QFN48; Packing Size: 250; Packing Type: TAPE_&_REEL; Part Number: 18-28499; Part Type: IC\MICROCONTROLLER\TEXAS_INSTRUMENTS; Revision: R003; RoHS Status: ROHS_COMPLIANT; Rtd Voltage: 3.8V; WEIGHT: 0.1336g; Color: Default; Design_Date : 2013-02-14; Designed_By : Artur Bielinski; Location X-Coordinate: 0; Location Y-Coordinate: 0; Power Pins Visible: False; Primitive: DEFAULT; SPLIT_INST: TRUE; SWAP_INFO: (S1+S2)
U2 = IC_RF_CC2592_QFN16_V1: IC, ANALOG, 2.4GHz RF FRONT END, 2V TO 3.7V, QFN16, SMD; ALT_SYMBOLS: QFNFC65P400X400X100-17AL,QFNFC65P400X400X100-17AM; AutoDoc File: http://notefied-dynamic-precision.com/DB/Apps/Desktop/Item/Object.aspx?id=89421; Budget Currency: USD; Budget Price: 1.38; Datasheet URL 1: http://www.ti.com/litv/pdf/mpqf121e; Datasheet URL 2: http://www.ti.com/lit/ds/symlink/cc2592.pdf; Definied Quality: INDUSTRIAL; Esd Level: HBM 2kV; Frequency: 2.4GHz; Last Time Buy: N/A; Lead Time: 10; LifeCycle Status: ACTIVE; MPN: CC2592RGVT; MPN Status: ACTIVE; MSL: 2; MTBF: 3.19*10^8; MTBF Standard: CL=60%,Tu=55degC,Ea=0.7eV,Tt=125degC; Manufacturer: TEXAS INSTRUMENTS; Max Oper Temp: +125DEGC; Min Oper Temp: -40DEGC; Mounting Type: SMD; NOTE Status: PREFERRED; PCB Package: QFN16; Packing Size: 250; Packing Type: TAPE_&_REEL; Part Number: 18-28661; Part Type: IC\ANALOG\RF\TRANSCEIVER; Revision: R002; RoHS Status: ROHS_COMPLIANT; Rtd Voltage: 2V TO 3.7V; WEIGHT: 0.0416g
Y1 = CRYSTAL: CRYSTAL, RESONATOR, 32.768kHz, -40DEGC/+85DEGC, SMD; ALT_SYMBOLS: XTAL_FC-135L,XTAL_FC-135M; AutoDoc File: http://notefied-dynamic-precision.com/DB/Apps/Desktop/Item/Object.aspx?id=91966; Budget Currency: EUR; Budget Price: 0.61; Capacitance: 7pF; Datasheet URL 1: http://www.eea.epson.com/portal/pls/portal/docs/1/1697492.PDF; Datasheet URL 2: http://www.epsondevice.com/docs/qd/en/DownloadServlet?id=ID000805; Definied Quality: INDUSTRIAL; Esd Level: N/A; FPLIST: XTAL_FC-135N,XTAL_FC-135L,XTAL_FC-135M; Last Time Buy: N/A; Lead Time: 8; LifeCycle Status: ACTIVE; MPN: FC-135 32.7680KA-AG0; MPN Status: ACTIVE; MSL: N/A; MTBF: N/A; MTBF Standard: N/A; Manufacturer: EPSON; Max Oper Temp: +85DEGC; Max TC: N/A; Max Tol: +20PPM; Min Oper Temp: -40DEGC; Min TC: N/A; Min Tol: -20PPM; Mounting Type: SMD; NOTE Status: PREFERRED; Packing Size: 1000; Packing Type: TAPE_&_REEL; Part Number: 12-00546; Part Type: CRYSTAL\RESONATOR; Revision: R001; RoHS Status: ROHS_COMPLIANT; Rtd Voltage: N/A; WEIGHT: N/A
Y2 = XTAL_4PIN_S: CRYSTAL, RESONATOR, 24MHz, -15PPM/+15PPM, -40DEGC/+85DEGC, SMD; ALT_SYMBOLS: OSCCC250X320X60-4L,OSCCC250X320X60-4M; AutoDoc File: http://notefied-dynamic-precision.com/DB/Apps/Desktop/Item/Object.aspx?id=96738; Budget Currency: EUR; Budget Price: 0.29; Capacitance: 9pF; Datasheet URL 1: http://www.eea.epson.com/portal/pls/portal/docs/1/1721495.PDF; Datasheet URL 2: http://www.eea.epson.com/portal/pls/portal/docs/1/1721499.PDF; Definied Quality: INDUSTRIAL; Esd Level: N/A; FPLIST: OSCCC250X320X60-4N,OSCCC250X320X60-4L,OSCCC250X320X60-4M; Last Time Buy: N/A; Lead Time: 8; LifeCycle Status: ACTIVE; MPN: TSX-3225 24.0000MF15X-AC3; MPN Status: ACTIVE; MSL: N/A; MTBF: N/A; MTBF Standard: N/A; Manufacturer: EPSON; Max Oper Temp: +85DEGC; Max TC: +15PPM; Max Tol: +10PPM; Min Oper Temp: -40DEGC; Min TC: -15PPM; Min Tol: -10PPM; Mounting Type: SMD; NOTE Status: PREFERRED; Packing Size: 250; Packing Type: TAPE_&_REEL; Part Number: 12-00757; Part Type: CRYSTAL\RESONATOR; Revision: R001; RoHS Status: ROHS_COMPLIANT; Rtd Voltage: N/A; WEIGHT: N/A

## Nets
GND: A1.2(GND) A1.3(GND) C1.2 C2.2 C3.2 C4.2 C5.2 C6.2 C7.2 C8.2 C9.2 C10.2 C11.2 C12.2 C13.2 C14.2 C15.2 C16.2 C17.2 C18.2 C19.2 C20.2 C21.2 C22.2 C23.2 C25.2 C26.2 C28.2 C29.2 C32.2 C36.1 C37.1 C38.1 J1.M1 J1.M2 P1.1 P1.19 P2.2 P2.20 R2.1 SC2.1(GND) SC2.2(GND) SC2.3(GND) SC2.4(GND) SC2.5(GND) SC2.6(GND) SC2.7(GND) SC2.8(GND) U1.49(VSS) U2.1(GND) U2.4(GND) U2.9(GND) U2.11(GND) U2.12(GND) U2.16(GND) U2.17(EGP/GND) Y2.2 Y2.4
VDD_CC2592: C11.1 C16.1 C19.1 C21.1 C25.1 C26.1 C32.1 FL2.1 L2.1 U2.13(VDD_LNA) U2.14(VDD_BIAS) U2.15(VDD_PA)
VDD_EB: FL1.2 FL2.2 P2.7 P2.9
VDDR: C1.1 C8.1 C9.1 C10.1 L1.2 U1.45(VDDR) U1.48(VDDR)
VDDS: C2.1 C3.1 C4.1 C5.1 C6.1 C7.1 FL1.1 R1.2 U1.13(VDDS2) U1.22(VDDS3) U1.34(VDDS_DCDC) U1.44(VDDS)
DCDC_SW: L1.1 U1.33(DCDC_SW)
DIO_0: P1.3 U1.5(DIO_0)
DIO_1: P1.5 U1.6(DIO_1)
DIO_2: P1.7 U1.7(DIO_2)
DIO_3: P1.9 U1.8(DIO_3)
DIO_4: P1.11 U1.9(DIO_4)
DIO_5: P1.13 U1.10(DIO_5)
DIO_6: P1.4 U1.11(DIO_6)
DIO_7: C38.2 R13.2 U1.12(DIO_7)
DIO_8: P1.20 U1.14(DIO_8)
DIO_9: P1.18 U1.15(DIO_9)
DIO_10: P1.16 U1.16(DIO_10)
DIO_11: P1.14 U1.17(DIO_11)
DIO_12: P1.12 U1.18(DIO_12)
DIO_13: C37.2 R14.2 U1.19(DIO_13)
DIO_14: C36.2 R15.2 U1.20(DIO_14)
DIO_15: P1.6 U1.21(DIO_15)
DIO_16 / JTAG TDO: P2.19 U1.26(DIO_16)
DIO_17 / JTAG TDI: P2.17 U1.27(DIO_17)
DIO_18: P1.8 U1.28(DIO_18)
DIO_19: P1.10 U1.29(DIO_19)
DIO_20: P2.8 U1.30(DIO_20)
DIO_21: P2.18 U1.31(DIO_21)
DIO_22: DIO22.1 U1.32(DIO_22)
DIO_23: P2.5 U1.36(DIO_23)
DIO_24: P2.10 U1.37(DIO_24)
DIO_25: P2.11 U1.38(DIO_25)
DIO_26: P2.6 U1.39(DIO_26)
DIO_27: P2.13 U1.40(DIO_27)
DIO_28: P2.16 U1.41(DIO_28)
DIO_29: P2.14 U1.42(DIO_29)
DIO_30: P2.12 U1.43(DIO_30)
JTAG_TCK: P2.1 U1.25(JTAG_TCKC)
JTAG_TMS: P2.4 U1.24(JTAG_TMSC)
nRESET: C20.1 P2.15 R1.1 U1.35(RESET_N)
N310466: C23.1 U1.47(X24M_P) Y2.1
N310868: C22.1 U1.46(X24M_N) Y2.3
N314494: L3.1 U1.1(RF_P) U2.3(RF_P)
N314505: L3.2 U1.2(RF_N) U2.2(RF_N)
N314786: C12.1 L2.2 L4.1 U2.10(ANT)
N315193: C13.1 L4.2 L13.1
N316022: A1.1(FEED) C15.1 C27.2
N316040: C24.1 J1.1
N316649: C28.1 U1.23(DCOUPL)
N316919: C17.1 U1.3(X32K_Q1) Y1.1
N316932: C18.1 U1.4(X32K_Q2) Y1.2
N334495: C14.1 C24.2 C27.1 L13.2
N435366: R15.1 U2.7(HGM)
N435370: R14.1 U2.6(LNA_EN)
N435374: R13.1 U2.5(PA_EN)
N443687: C29.1 R2.2 U2.8(BIAS)

Not connected (* = marked no-connect by the designer): FIDU1 1*; FIDU2 1*; FIDU3 1*; FIDU4 1*; FIDU5 1*; FIDU6 1*; P1 2* 15* 17*; P2 3*

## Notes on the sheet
- VDDS Decoupling Capacitors for CC2650
- VDDR Decoupling Capacitors for CC2650
- Pin 45
- Pin 48
- Pin 13
- Pin 22
- Pin 44
- Pin 34
- Place L1 and
  C8 close to pin 33
- Mount either C24 or C27
  To select SMA or PCB ant.
  Note that a DC-blocking
  capacitor must be used if
  antenna has DC-path
  to ground.
- NOTE:
  The CC2650 is a superset of CC2610, CC2620, CC2630
  and CC2640. This design can thus be considered a
  reference design for all of these devices.
  Likewise, the CC2650EM board can be used to evaluate
  the performance for all the above mentioned devices.
- EM connector 1
- EM connector 2
